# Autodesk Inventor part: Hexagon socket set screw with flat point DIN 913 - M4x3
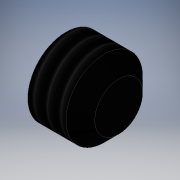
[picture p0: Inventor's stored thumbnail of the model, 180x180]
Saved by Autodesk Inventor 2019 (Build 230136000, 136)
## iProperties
Created: 2022-11
Part Number: Hexagon socket set screw with flat point DIN 913 - M4x3
Material: Generic
Catalog Web Link: www.cadenas.de
Description: DIN 913-Hexagon socket set screw with flat point
Vendor: MISUMI
Document SubType Name: Modeling
Designer: psAdmin
Manufacturer: MISUMI
Mass: 0.0287636 g
Surface Area: 0.64306 cm^2
Volume: 0.0287636 cm^3
Density: 1 g/cm^3
Appearance: PSOLRGB-55-55-55
Category: PARTsolutions
Company: MISUMI
Title: Hexagon socket set screw with flat point DIN 913 - M4x3
Author: Cadenas PARTsolutions
Comments: Hexagon socket set screw with flat point
PSOL_IDENT_0: {$CADENAS_DATA/23d-libs/misumi/metric/accessories/din_913.prj},252 {VTYP=3D},{NB=Hexagon socket set
PSOL_IDENT_1: screw with flat point DIN 913 - M4x3},{LINA=Hexagon socket set screw with flat point DIN 913 - M4x3}
PSOL_IDENT_2: ,{NN=DIN 913},{DATE=30.11.2021 06:37:25},{GEOMDATE=17.02.2014 00:00:00},{VERSION=},{LINEID=320},{WBV
PSOL_IDENT_3: AR=},{WBNUMERIC=}  {NB=Gewindestift DIN 913 - M4x3},{LINA=Gewindestift DIN 913 - M4x3},{KT=X},{IDNR=
PSOL_IDENT_4: },{NENN=M4x3},{D=4.000},{D3=3.141},{P=0.700},{L=3.000},{DP=2.500},{S=2.000},{T=1.500}
NB: Headless pin DIN 913 - M4x3
NN: DIN 913
NT: Hexagon socket set screw with flat point
NBSYN: Headless pin DIN 913 - $NENN.
LINA: Headless pin DIN 913 - M4x3
CATALOG: Misumi
ROWDESC: M4x3
D: 4
D3: 3.141
P: 0.7
L: 3
DP: 2.5
S: 2
T: 1.5
SUPPLIER: MISUMI
ARTICLENO: Hexagon socket set screw with flat point DIN 913 - M4x3
BOMINFO: Hexagon socket set screw with flat point DIN 913 - M4x3
CREATOR: CADENAS GmbH
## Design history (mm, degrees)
sketch "Sketch_1"
  geometry: L1 (0.667, 0)-(3, 0); L2 (3, 0)-(3, -1.25); L3 (3, -1.25)-(2.25, -2); L4 (2.25, -2)-(0.248, -2); L5 (0.248, -2)-(0, -1.571); L6 (0, -1.571)-(0, -1.155); L7 (0, -1.155)-(0.667, 0); L8 (0.667, 0)-(3, 0)
  constraints: 16 end point
revolve "Revolution1" sketch "Sketch_1" stored, may be unused: angle "d0" = 360 deg
thread "Thread1" dims "d1" = 2.00203, "d2" = 0
sketch "Sketch_2"
  geometry: L1 (0, 1.155)-(-1, 0.577); L2 (-1, 0.577)-(-1, -0.577); L3 (-1, -0.577)-(0, -1.155); L4 (0, -1.155)-(1, -0.577); L5 (1, -0.577)-(1, 0.577); L6 (1, 0.577)-(0, 1.155)
  constraints: 12 end point
extrude "Extrusion1" cut sketch "Sketch_2" distance "d3" = 1.5; taper "d4" = 0 deg
node "IP1_XY"
node "IP1_YZ"
node "IP1_ZX"
node "IP1_X"
node "IP1_Y"
node "IP1_Z"
node "IP1_Center"
node "IP2_XY"
node "IP2_YZ"
node "IP2_ZX"
node "IP2_X"
node "IP2_Y"
node "IP2_Z"
node "IP2_Center"
body "Solid1"
other parameters: "d5" = 0, "d6" = 0
